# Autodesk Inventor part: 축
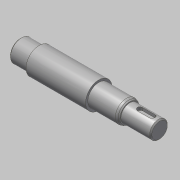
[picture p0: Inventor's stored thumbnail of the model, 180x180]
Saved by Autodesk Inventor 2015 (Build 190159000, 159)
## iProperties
Created: 2016-06
Part Number: 축
Material: 강철, 연강
Document SubType Name: Modeling
Designer: mduedu
Density: 7.86 g/cm^3
Appearance: 강철
Author: mduedu
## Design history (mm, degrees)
sketch "스케치1"
  geometry: L1 (-63, 0)-(63, 0); L2 (-63, 0)-(-63, 10); L3 (-63, 10)-(-46, 10); L4 (-46, 10)-(-46, 12); L5 (-46, 12)-(8, 12); L6 (8, 12)-(8, 10); L7 (8, 10)-(36, 10); L8 (36, 10)-(36, 8); L9 (36, 8)-(63, 8); L10 (63, 8)-(63, 0); 2 further points
  constraints: 20 end point, 5 parallel, 2 perpendicular, 1 coincident, 1 collinear, 1 horizontal, 1 midpoint, 1 vertical
  dimensions: "d0" = 126 distance of L1.start L1.end; "d2" = 16 diameter of L9 L1; "d3" = 20 diameter of L7 L1; "d4" = 24 diameter of L5 L1; "d5" = 20 diameter of L3 L1; "d6" = 17 distance of L2.end L3.end; "d7" = 27 distance of L8.end L9.end; "d8" = 55 distance from line of L5.end L10
revolve "회전1" sketch "스케치1" stored, may be unused: angle "d9" = 90 deg
chamfer "모따기1" distance "d10" = 2; stored, may be unused: second distance "d11" = 2, angle "d12" = 30 deg
fillet "모깎기1" dims "d13" = 4
node "작업 평면1"
sketch "스케치2"
  geometry: L1 (-4, 2.5)-(7, 2.5); L2 (7, -2.5)-(-4, -2.5); L3 (-4, 0)-(7, 0); L4 (-13.5, 8.845)-(-13.5, -8.845) reference; A1 r 2.5 centre (-4, 0) between (-4, 2.5) and (-4, -2.5); A2 r 2.5 centre (7, 0) between (7, -2.5) and (7, 2.5); 1 further point
  constraints: 6 end point, 4 point on circle, 3 tangent, 2 centre point, 2 parallel, 1 horizontal, 1 horizontal alignment
  dimensions: "d14" = 7 distance edge to line of A1 L4; "d15" = 5 distance between parallel lines of L2 L1; "d16" = 16 dimension on A2 A1
extrude "돌출1" cut sketch "스케치2" distance "d17" = 3; taper "d18" = 0 deg
chamfer "모따기2" distance "d19" = 1; stored, may be unused: second distance "d20" = 2, angle "d21" = 30 deg
sketch "스케치3"
  geometry: L1 (-36, -8)-(-62, -8) reference; L2 (-63, -7)-(-63, 7) reference; L3 (-39.5, -8)-(-41, -6.5); L4 (-41, -6.5)-(-41, -8); L5 (-39.5, -8)-(-41, -8); 1 further point
  constraints: 6 end point, 2 point on line, 1 collinear, 1 vertical
  dimensions: "d22" = 45 deg angle of L4 L3; "d23" = 22 distance between parallel lines of L2 L4; "d24" = 3 diameter of L3.start L4
revolve "회전2" stored, may be unused: angle "d25" = 90 deg
node "작업점1"
sketch "스케치4"
  geometry: 1 further point
hole "구멍1" sketch "스케치4" at (0, 0) diameter "d26" = 3.242; stored, may be unused: countersink angle "d30" = 90 deg, drill point angle "d32" = 120 deg; dims "d27" = 8, "d28" = 4, "d29" = 2, "d31" = 11
chamfer "모따기3" distance "d33" = 2; stored, may be unused: second distance "d34" = 2, angle "d35" = 30 deg
node "솔리드1"
